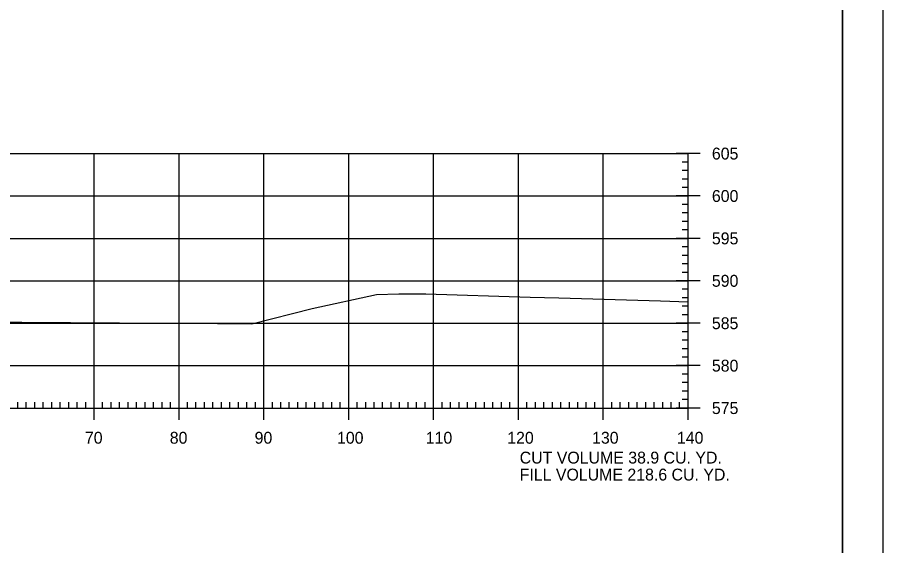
# Model space of a CAD drawing. Extents: x 961436 to 1372525, y 380079 to 2027791.
# Drawn here: x 1371255.8 to 1371357.8, y 380197.8 to 380260.1 of the extents above; entities that cross this region are included whole.
import ezdxf

# ---------------------------------------------------------------- set-up
doc = ezdxf.new("R2010")
doc.units = 0
for name, color, linetype in [('R_Axis', 7, 'Continuous'), ('R_Axis Annot', 7, 'Continuous'), ('R_Border', 7, 'Continuous'), ('R_Exist Surface', 7, 'Continuous'), ('R_Grid', 7, 'Continuous'), ('R_No Plot', 7, 'Continuous')]:
    doc.layers.add(name, color=color, linetype=linetype)

msp = doc.modelspace()

# ---------------------------------------------------------------- linework, layer by layer
at = {"layer": 'R_Axis'}
for p, q in [((1371336.28, 380244.06), (1371333.48, 380244.06)), ((1371334.88, 380214.06), (1371334.88, 380244.06)), ((1371334.88, 380243.06), (1371334.18, 380243.06)), ((1371334.88, 380242.06), (1371334.18, 380242.06)), ((1371334.88, 380241.06), (1371334.18, 380241.06)), ((1371334.88, 380240.06), (1371334.18, 380240.06)), ((1371336.28, 380239.06), (1371333.48, 380239.06)), ((1371334.88, 380238.06), (1371334.18, 380238.06)), ((1371334.88, 380237.06), (1371334.18, 380237.06)), ((1371334.88, 380236.06), (1371334.18, 380236.06)), ((1371334.88, 380235.06), (1371334.18, 380235.06)), ((1371336.28, 380234.06), (1371333.48, 380234.06)), ((1371334.88, 380233.06), (1371334.18, 380233.06)), ((1371334.88, 380232.06), (1371334.18, 380232.06)), ((1371334.88, 380231.06), (1371334.18, 380231.06)), ((1371334.88, 380230.06), (1371334.18, 380230.06)), ((1371336.28, 380229.06), (1371333.48, 380229.06)), ((1371334.88, 380228.06), (1371334.18, 380228.06)), ((1371334.88, 380227.06), (1371334.18, 380227.06)), ((1371334.88, 380226.06), (1371334.18, 380226.06)), ((1371334.88, 380225.06), (1371334.18, 380225.06)), ((1371336.28, 380224.06), (1371333.48, 380224.06)), ((1371334.88, 380223.06), (1371334.18, 380223.06)), ((1371334.88, 380222.06), (1371334.18, 380222.06)), ((1371334.88, 380221.06), (1371334.18, 380221.06)), ((1371334.88, 380220.06), (1371334.18, 380220.06)), ((1371336.28, 380219.06), (1371333.48, 380219.06)), ((1371334.88, 380218.06), (1371334.18, 380218.06)), ((1371334.88, 380217.06), (1371334.18, 380217.06)), ((1371334.88, 380216.06), (1371334.18, 380216.06)), ((1371264.88, 380212.66), (1371264.88, 380215.46)), ((1371274.88, 380212.66), (1371274.88, 380215.46)), ((1371284.88, 380212.66), (1371284.88, 380215.46)), ((1371294.88, 380212.66), (1371294.88, 380215.46)), ((1371304.88, 380212.66), (1371304.88, 380215.46)), ((1371314.88, 380212.66), (1371314.88, 380215.46)), ((1371324.88, 380212.66), (1371324.88, 380215.46)), ((1371334.88, 380215.06), (1371334.18, 380215.06)), ((1371334.88, 380212.66), (1371334.88, 380215.46)), ((1371054.88, 380214.06), (1371334.88, 380214.06)), ((1371255.88, 380214.06), (1371255.88, 380214.76)), ((1371256.88, 380214.06), (1371256.88, 380214.76)), ((1371257.88, 380214.06), (1371257.88, 380214.76)), ((1371258.88, 380214.06), (1371258.88, 380214.76)), ((1371259.88, 380214.06), (1371259.88, 380214.76)), ((1371260.88, 380214.06), (1371260.88, 380214.76)), ((1371261.88, 380214.06), (1371261.88, 380214.76)), ((1371262.88, 380214.06), (1371262.88, 380214.76)), ((1371263.88, 380214.06), (1371263.88, 380214.76)), ((1371265.88, 380214.06), (1371265.88, 380214.76)), ((1371266.88, 380214.06), (1371266.88, 380214.76)), ((1371267.88, 380214.06), (1371267.88, 380214.76)), ((1371268.88, 380214.06), (1371268.88, 380214.76)), ((1371269.88, 380214.06), (1371269.88, 380214.76)), ((1371270.88, 380214.06), (1371270.88, 380214.76)), ((1371271.88, 380214.06), (1371271.88, 380214.76)), ((1371272.88, 380214.06), (1371272.88, 380214.76)), ((1371273.88, 380214.06), (1371273.88, 380214.76)), ((1371275.88, 380214.06), (1371275.88, 380214.76)), ((1371276.88, 380214.06), (1371276.88, 380214.76)), ((1371277.88, 380214.06), (1371277.88, 380214.76)), ((1371278.88, 380214.06), (1371278.88, 380214.76)), ((1371279.88, 380214.06), (1371279.88, 380214.76)), ((1371280.88, 380214.06), (1371280.88, 380214.76)), ((1371281.88, 380214.06), (1371281.88, 380214.76)), ((1371282.88, 380214.06), (1371282.88, 380214.76)), ((1371283.88, 380214.06), (1371283.88, 380214.76)), ((1371285.88, 380214.06), (1371285.88, 380214.76)), ((1371286.88, 380214.06), (1371286.88, 380214.76)), ((1371287.88, 380214.06), (1371287.88, 380214.76)), ((1371288.88, 380214.06), (1371288.88, 380214.76)), ((1371289.88, 380214.06), (1371289.88, 380214.76)), ((1371290.88, 380214.06), (1371290.88, 380214.76)), ((1371291.88, 380214.06), (1371291.88, 380214.76)), ((1371292.88, 380214.06), (1371292.88, 380214.76)), ((1371293.88, 380214.06), (1371293.88, 380214.76)), ((1371295.88, 380214.06), (1371295.88, 380214.76)), ((1371296.88, 380214.06), (1371296.88, 380214.76)), ((1371297.88, 380214.06), (1371297.88, 380214.76)), ((1371298.88, 380214.06), (1371298.88, 380214.76)), ((1371299.88, 380214.06), (1371299.88, 380214.76)), ((1371300.88, 380214.06), (1371300.88, 380214.76)), ((1371301.88, 380214.06), (1371301.88, 380214.76)), ((1371302.88, 380214.06), (1371302.88, 380214.76)), ((1371303.88, 380214.06), (1371303.88, 380214.76)), ((1371305.88, 380214.06), (1371305.88, 380214.76)), ((1371306.88, 380214.06), (1371306.88, 380214.76)), ((1371307.88, 380214.06), (1371307.88, 380214.76)), ((1371308.88, 380214.06), (1371308.88, 380214.76)), ((1371309.88, 380214.06), (1371309.88, 380214.76)), ((1371310.88, 380214.06), (1371310.88, 380214.76)), ((1371311.88, 380214.06), (1371311.88, 380214.76)), ((1371312.88, 380214.06), (1371312.88, 380214.76)), ((1371313.88, 380214.06), (1371313.88, 380214.76)), ((1371315.88, 380214.06), (1371315.88, 380214.76)), ((1371316.88, 380214.06), (1371316.88, 380214.76)), ((1371317.88, 380214.06), (1371317.88, 380214.76)), ((1371318.88, 380214.06), (1371318.88, 380214.76)), ((1371319.88, 380214.06), (1371319.88, 380214.76)), ((1371320.88, 380214.06), (1371320.88, 380214.76)), ((1371321.88, 380214.06), (1371321.88, 380214.76)), ((1371322.88, 380214.06), (1371322.88, 380214.76)), ((1371323.88, 380214.06), (1371323.88, 380214.76)), ((1371325.88, 380214.06), (1371325.88, 380214.76)), ((1371326.88, 380214.06), (1371326.88, 380214.76)), ((1371327.88, 380214.06), (1371327.88, 380214.76)), ((1371328.88, 380214.06), (1371328.88, 380214.76)), ((1371329.88, 380214.06), (1371329.88, 380214.76)), ((1371330.88, 380214.06), (1371330.88, 380214.76)), ((1371331.88, 380214.06), (1371331.88, 380214.76)), ((1371332.88, 380214.06), (1371332.88, 380214.76)), ((1371336.28, 380214.06), (1371333.48, 380214.06)), ((1371333.88, 380214.06), (1371333.88, 380214.76))]:
    msp.add_line(p, q, dxfattribs=at)
at = {"layer": 'R_Border'}
msp.add_line((1371353.06, 380113.06), (1371353.06, 380318.52), dxfattribs=at)
at = {"layer": 'R_Exist Surface'}
msp.add_lwpolyline([(1371244.76, 380224.26), (1371279.4, 380224.01), (1371283.46, 380223.98), (1371290.58, 380225.8), (1371298.17, 380227.44), (1371300.77, 380227.52), (1371303.96, 380227.53), (1371316.26, 380227.13), (1371319.66, 380227.06), (1371331.63, 380226.69), (1371334.88, 380226.59)], dxfattribs=at)
at = {"layer": 'R_Grid'}
for p, q in [((1371054.88, 380244.06), (1371334.88, 380244.06)), ((1371264.88, 380214.06), (1371264.88, 380244.06)), ((1371274.88, 380214.06), (1371274.88, 380244.06)), ((1371284.88, 380214.06), (1371284.88, 380244.06)), ((1371294.88, 380214.06), (1371294.88, 380244.06)), ((1371304.88, 380214.06), (1371304.88, 380244.06)), ((1371314.88, 380214.06), (1371314.88, 380244.06)), ((1371324.88, 380214.06), (1371324.88, 380244.06)), ((1371334.88, 380214.06), (1371334.88, 380244.06)), ((1371054.88, 380239.06), (1371334.88, 380239.06)), ((1371054.88, 380234.06), (1371334.88, 380234.06)), ((1371054.88, 380229.06), (1371334.88, 380229.06)), ((1371054.88, 380224.06), (1371334.88, 380224.06)), ((1371054.88, 380219.06), (1371334.88, 380219.06)), ((1371054.88, 380214.06), (1371334.88, 380214.06))]:
    msp.add_line(p, q, dxfattribs=at)
at = {"layer": 'R_No Plot'}
for points in [[(1371024.47, 380322.41), (1371357.81, 380322.41), (1371357.81, 380109.08), (1371024.47, 380109.08)], [(1371270.8, 380318.52), (1371290.42, 380318.52), (1371290.42, 380308.64), (1371306.53, 380308.64), (1371329.73, 380308.64), (1371329.85, 380280.48), (1371353.06, 380280.48), (1371353.06, 380113.06), (1371036.88, 380113.06), (1371036.88, 380318.52)]]:
    msp.add_lwpolyline(points, close=True, dxfattribs=at)

# ---------------------------------------------------------------- texts
at = {"layer": 'R_Axis Annot'}
for s, p in [('605', (1371337.68, 380243.36)), ('600', (1371337.68, 380238.36)), ('595', (1371337.68, 380233.36)), ('590', (1371337.68, 380228.36)), ('585', (1371337.68, 380223.36)), ('580', (1371337.68, 380218.36)), ('575', (1371337.68, 380213.36)), ('70', (1371263.79, 380209.86)), ('80', (1371273.79, 380209.86)), ('90', (1371283.79, 380209.86)), ('100', (1371293.5, 380209.86)), ('110', (1371303.96, 380209.86)), ('120', (1371313.56, 380209.86)), ('130', (1371323.56, 380209.86)), ('140', (1371333.56, 380209.86)), ('CUT VOLUME 38.9 CU. YD.', (1371315.03, 380207.52)), ('FILL VOLUME 218.6 CU. YD.', (1371315.03, 380205.52))]:
    msp.add_text(s, height=1.4, dxfattribs=at).set_placement(p)

doc.saveas('drawing.dxf')
